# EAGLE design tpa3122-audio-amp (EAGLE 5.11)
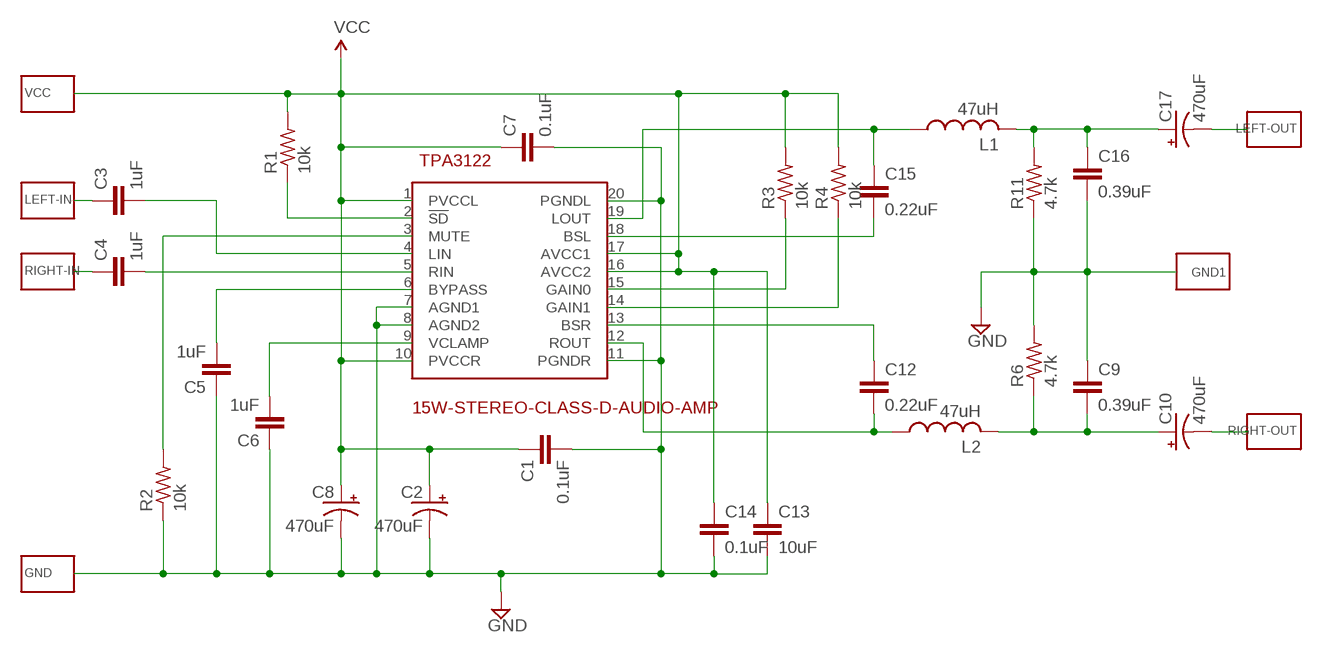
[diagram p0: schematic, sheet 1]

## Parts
15W-STEREO-CLASS-D-AUDIO-AMP  TPA3122  [DIL20]
C1  0.1uF  C-EUC1206  [C1206]
C2  470uF  CPOL-USE5-10.5  [E5-10,5]
C3  1uF  C-EUC1206  [C1206]
C4  1uF  C-EUC1206  [C1206]
C5  1uF  C-EUC1206  [C1206]
C6  1uF  C-EUC1206  [C1206]
C7  0.1uF  C-EUC1206  [C1206]
C8  470uF  CPOL-USE5-10.5  [E5-10,5]
C9  0.39uF  C-EUC1206  [C1206]
C10  470uF  CPOL-USE5-10.5  [E5-10,5]
C12  0.22uF  C-EU050-025X075  [C050-025X075]
C13  10uF  C-EUC1206  [C1206]
C14  0.1uF  C-EUC1206  [C1206]
C15  0.22uF  C-EU050-025X075  [C050-025X075]
C16  0.39uF  C-EUC1206  [C1206]
C17  470uF  CPOL-USE5-10.5  [E5-10,5]
GND  WIREPAD-SMD-NO-VALUE  [WIREPAD-SMD]
GND1  WIREPAD-SMD-NO-VALUE  [WIREPAD-SMD]
L1  47uH  L-US0207/5V  [0207/5V]
L2  47uH  L-US0207/5V  [0207/5V]
LEFT-IN  WIREPAD-SMD-NO-VALUE  [WIREPAD-SMD]
LEFT-OUT  WIREPAD-SMD-NO-VALUE  [WIREPAD-SMD]
R1  10k  R-US_R1210  [R1210]
R2  10k  R-US_R1210  [R1210]
R3  10k  R-US_R1210  [R1210]
R4  10k  R-US_R1210  [R1210]
R6  4.7k  R-US_R1206  [R1206]
R11  4.7k  R-US_R1206  [R1206]
RIGHT-IN  WIREPAD-SMD-NO-VALUE  [WIREPAD-SMD]
RIGHT-OUT  WIREPAD-SMD-NO-VALUE  [WIREPAD-SMD]
VCC  WIREPAD-SMD-NO-VALUE  [WIREPAD-SMD]

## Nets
GND: 15W-STEREO-CLASS-D-AUDIO-AMP.7(AGND1) 15W-STEREO-CLASS-D-AUDIO-AMP.8(AGND2) 15W-STEREO-CLASS-D-AUDIO-AMP.11(PGNDR) 15W-STEREO-CLASS-D-AUDIO-AMP.20(PGNDL) C1.2 C2.- C5.1 C6.1 C7.2 C8.- C9.1 C13.2 C14.2 C16.2 GND1.1(P) GND.1(P) R2.1 R6.2 R11.1
N$1: 15W-STEREO-CLASS-D-AUDIO-AMP.12(ROUT) C12.2 L2.1
N$2: 15W-STEREO-CLASS-D-AUDIO-AMP.14(GAIN1) R4.1
N$3: C3.1 LEFT-IN.1(P)
N$4: 15W-STEREO-CLASS-D-AUDIO-AMP.13(BSR) C12.1
N$5: C16.1 C17.+ L1.2 R11.2
N$6: C9.2 C10.+ L2.2 R6.1
N$7: 15W-STEREO-CLASS-D-AUDIO-AMP.19(LOUT) C15.1 L1.1
N$8: 15W-STEREO-CLASS-D-AUDIO-AMP.18(BSL) C15.2
N$9: 15W-STEREO-CLASS-D-AUDIO-AMP.15(GAIN0) R3.1
N$10: 15W-STEREO-CLASS-D-AUDIO-AMP.9(VCLAMP) C6.2
N$11: 15W-STEREO-CLASS-D-AUDIO-AMP.6(BYPASS) C5.2
N$12: 15W-STEREO-CLASS-D-AUDIO-AMP.5(RIN) C4.2
N$13: 15W-STEREO-CLASS-D-AUDIO-AMP.4(LIN) C3.2
N$14: C4.1 RIGHT-IN.1(P)
N$15: C10.- RIGHT-OUT.1(P)
N$16: 15W-STEREO-CLASS-D-AUDIO-AMP.2(!SD) R1.1
N$17: C17.- LEFT-OUT.1(P)
N$18: 15W-STEREO-CLASS-D-AUDIO-AMP.3(MUTE) R2.2
VCC: 15W-STEREO-CLASS-D-AUDIO-AMP.1(PVCCL) 15W-STEREO-CLASS-D-AUDIO-AMP.10(PVCCR) 15W-STEREO-CLASS-D-AUDIO-AMP.16(AVCC2) 15W-STEREO-CLASS-D-AUDIO-AMP.17(AVCC1) C1.1 C2.+ C7.1 C8.+ C13.1 C14.1 R1.2 R3.2 R4.2 VCC.1(P)

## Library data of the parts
15W-STEREO-CLASS-D-AUDIO-AMP = trl:TPA3122
C1 C3-C7 C9 C12-C16 = resistor:C-EU: CAPACITOR, European symbol
C2 C8 C10 C17 = resistor:CPOL-US: POLARIZED CAPACITOR, American symbol
GND GND1 LEFT-IN LEFT-OUT RIGHT-IN RIGHT-OUT VCC = trl:WIREPAD-SMD-NO-VALUE
L1 L2 = rcl:L-US: INDUCTOR, American symbol
R1-R4 R6 R11 = resistor:R-US_: RESISTOR, American symbol

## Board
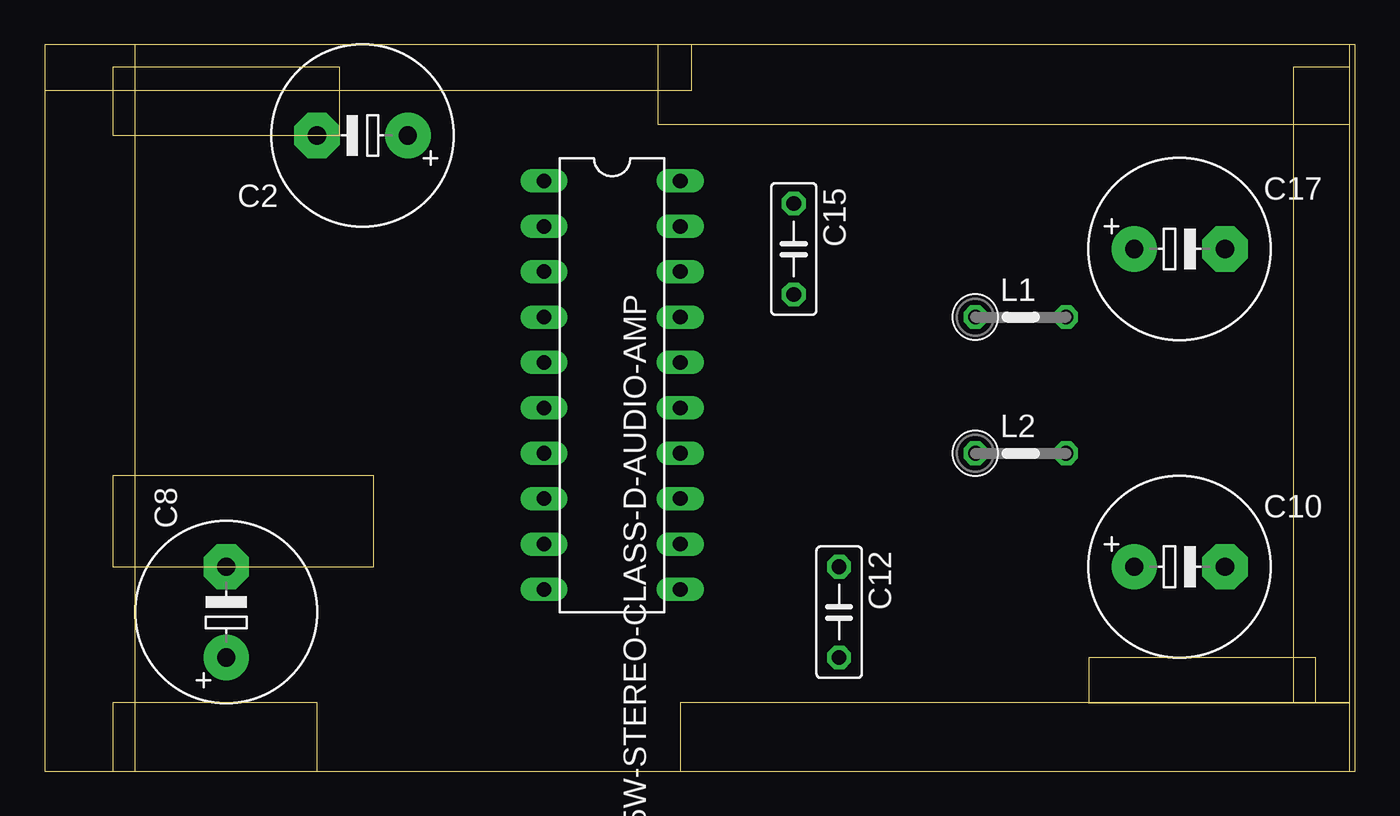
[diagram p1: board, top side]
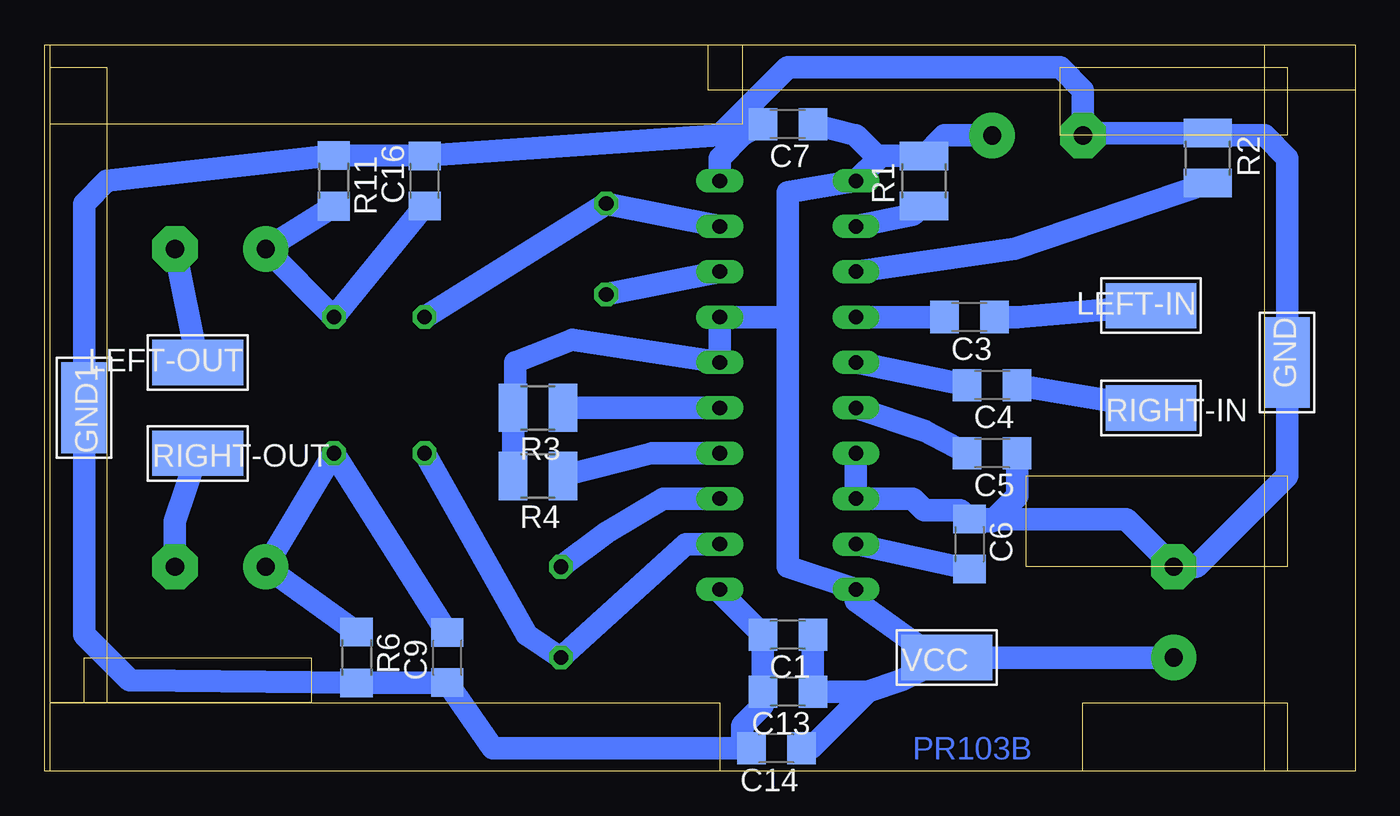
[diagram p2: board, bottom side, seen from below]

Size 73.33 x 40.63 mm. Coordinates in mm from the lower left corner, seen from the top.
Outline: 0,0 73.33,0 73.33,40.63 0,40.63 0,0
Copper layers (1*16): Top 0.035mm / dielectric 1.5mm / Bottom 0.035mm
Design rules "default": minimum track width 10mil, minimum drill 24mil, track to track 8mil, track to pad 8mil, pad to pad 8mil, via to via 8mil, smd to smd 8mil, copper to edge 40mil, drill to drill 8mil, minimum pad ring 10mil, minimum via ring 8mil, stop-mask expansion 4mil, vias tented up to drill 0mil, thermal gap 10mil
Milling: area 35.6,0 to 73,3.8; area 69.8,3.8 to 73,39.4; area 58.4,3.8 to 71.1,6.3; area 34.3,36.2 to 73,40.6; area 0,38.1 to 36.2,40.6; area 0,0 to 5.1,40.6; area 3.8,11.4 to 18.4,16.5; area 3.8,0 to 15.2,3.8; area 3.8,35.6 to 16.5,39.4

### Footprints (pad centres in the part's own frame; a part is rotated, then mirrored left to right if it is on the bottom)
DIL20 = drill 0.813 long: 1 -11.43,-3.81; 2 -8.89,-3.81; 3 -6.35,-3.81; 4 -3.81,-3.81; 5 -1.27,-3.81; 6 1.27,-3.81; 7 3.81,-3.81; 8 6.35,-3.81; 9 8.89,-3.81; 10 11.43,-3.81; 11 11.43,3.81; 12 8.89,3.81; 13 6.35,3.81; 14 3.81,3.81; 15 1.27,3.81; 16 -1.27,3.81; 17 -3.81,3.81; 18 -6.35,3.81; 19 -8.89,3.81; 20 -11.43,3.81
C1206 = smd 1.6 x 1.8: 1 -1.4,0; 2 1.4,0
E5-10,5 = drill 1.016 pad 2.54 round: + -2.54,0 | drill 1.016 pad 2.54 octagon: - 2.54,0
C050-025X075 = drill 0.813 octagon: 1 -2.54,0; 2 2.54,0
WIREPAD-SMD = smd 2.54 x 5.08: 1 0,0
0207/5V = drill 0.813 octagon: 1 -2.54,0; 2 2.54,0
R1210 = smd 1.6 x 2.7: 1 -1.4,0; 2 1.4,0
R1206 = smd 1.6 x 1.803: 1 -1.422,0; 2 1.422,0

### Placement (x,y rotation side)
15W-STEREO-CLASS-D-AUDIO-AMP  31.75,21.59 270 top
C1  31.75,7.62 180 bottom
C2  17.78,35.56 180 top
C3  21.59,25.4 180 bottom
C4  20.32,21.59 180 bottom
C5  20.32,17.78 180 bottom
C6  21.59,12.7 270 bottom
C7  31.75,36.2 180 bottom
C8  10.16,8.89 90 top
C9  50.8,6.35 90 bottom
C10  63.5,11.43 0 top
C12  44.45,8.89 270 top
C13  31.75,4.45 180 bottom
C14  32.38,1.27 180 bottom
C15  41.91,29.21 270 top
C16  52.07,33.02 90 bottom
C17  63.5,29.21 0 top
GND  3.81,22.86 180 bottom
GND1  71.12,20.32 0 bottom
L1  54.61,25.4 0 top
L2  54.61,17.78 0 top
LEFT-IN  11.43,26.04 90 bottom
LEFT-OUT  64.77,22.86 90 bottom
R1  24.13,33.02 90 bottom
R2  8.26,34.29 270 bottom
R3  45.72,20.32 180 bottom
R4  45.72,16.51 180 bottom
R6  55.88,6.35 270 bottom
R11  57.15,33.02 270 bottom
RIGHT-IN  11.43,20.32 270 bottom
RIGHT-OUT  64.77,17.78 270 bottom
VCC  22.86,6.35 270 bottom

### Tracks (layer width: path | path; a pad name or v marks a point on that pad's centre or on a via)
GND
  Bottom 1.27: 15W-STEREO-CLASS-D-AUDIO-AMP.7 15W-STEREO-CLASS-D-AUDIO-AMP.8 24.77,15.24 24.13,14.61 22.09,14.61 C6.1 | 15W-STEREO-CLASS-D-AUDIO-AMP.11 35.56,10.03 C1.2 C13.2 33.15,3.68 34.29,2.54 34.29,1.77 C14.2 48.26,1.27 C9.1 R6.2 68.58,5.08 71.12,7.62 71.12,19.05 GND1.1 71.12,31.75 69.85,33.02 R11.1 C16.2 35.56,35.56 | 34.29,35.56 C7.2 | 34.29,35.56 35.56,34.29 15W-STEREO-CLASS-D-AUDIO-AMP.20 | 35.56,35.56 34.29,35.56 | 35.56,35.56 31.75,39.37 16.51,39.37 15.24,38.1 C2.- 15.11,35.69 R2.1 8.12,35.56 5.08,35.56 3.81,34.29 GND.1 3.81,16.51 8.89,11.43 C8.- 12.83,14.1 C6.1 | C5.1 18.92,15.37 20.32,13.97 21.46,13.97 C6.1
N$1
  Bottom 1.27: L2.1 46.35,7.62 C12.2 37.47,12.7 15W-STEREO-CLASS-D-AUDIO-AMP.12
N$2
  Bottom 1.27: 15W-STEREO-CLASS-D-AUDIO-AMP.14 39.37,17.78 R4.1
N$3
  Bottom 1.27: LEFT-IN.1 18.92,25.4 C3.1
N$4
  Bottom 1.27: C12.1 41.91,13.34 38.73,15.24 15W-STEREO-CLASS-D-AUDIO-AMP.13
N$5
  Bottom 1.27: R11.2 C17.+ L1.2 C16.1
N$6
  Bottom 1.27: R6.1 C10.+ L2.2 C9.2
N$7
  Bottom 1.27: 15W-STEREO-CLASS-D-AUDIO-AMP.19 C15.1 L1.1
N$8
  Bottom 1.27: 15W-STEREO-CLASS-D-AUDIO-AMP.18 C15.2
N$9
  Bottom 1.27: R3.1 15W-STEREO-CLASS-D-AUDIO-AMP.15
N$10
  Bottom 1.27: 15W-STEREO-CLASS-D-AUDIO-AMP.9 C6.2
N$11
  Bottom 1.27: 15W-STEREO-CLASS-D-AUDIO-AMP.6 24.13,19.05 C5.2
N$12
  Bottom 1.27: 15W-STEREO-CLASS-D-AUDIO-AMP.5 C4.2
N$13
  Bottom 1.27: 15W-STEREO-CLASS-D-AUDIO-AMP.4 C3.2
N$14
  Bottom 1.27: C4.1 RIGHT-IN.1
N$15
  Bottom 1.27: C10.- 66.04,13.97 RIGHT-OUT.1
N$16
  Bottom 1.27: 15W-STEREO-CLASS-D-AUDIO-AMP.2 24.77,31.11 R1.1
N$17
  Bottom 1.27: LEFT-OUT.1 C17.-
N$18
  Bottom 1.27: 15W-STEREO-CLASS-D-AUDIO-AMP.3 19.05,29.21 R2.2
VCC
  Bottom 1.27: R4.2 R3.2 46.99,20.32 46.99,22.86 43.81,24.13 15W-STEREO-CLASS-D-AUDIO-AMP.16 15W-STEREO-CLASS-D-AUDIO-AMP.17 31.75,25.4 | 31.75,25.4 31.75,11.43 15W-STEREO-CLASS-D-AUDIO-AMP.10 27.94,9.53 23.5,6.35 VCC.1 | 31.75,25.4 31.75,32.38 15W-STEREO-CLASS-D-AUDIO-AMP.1 26.67,34.29 | 26.67,34.29 26.67,34.42 R1.2 22.99,35.56 C2.+ | C7.1 27.94,35.56 26.67,34.29 | C8.+ VCC.1 | C14.1 30.48,1.27 27.3,4.45 | 27.3,4.45 25.4,5.08 VCC.1 | 27.3,4.45 C13.1 C1.1

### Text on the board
Bottom: PR103B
